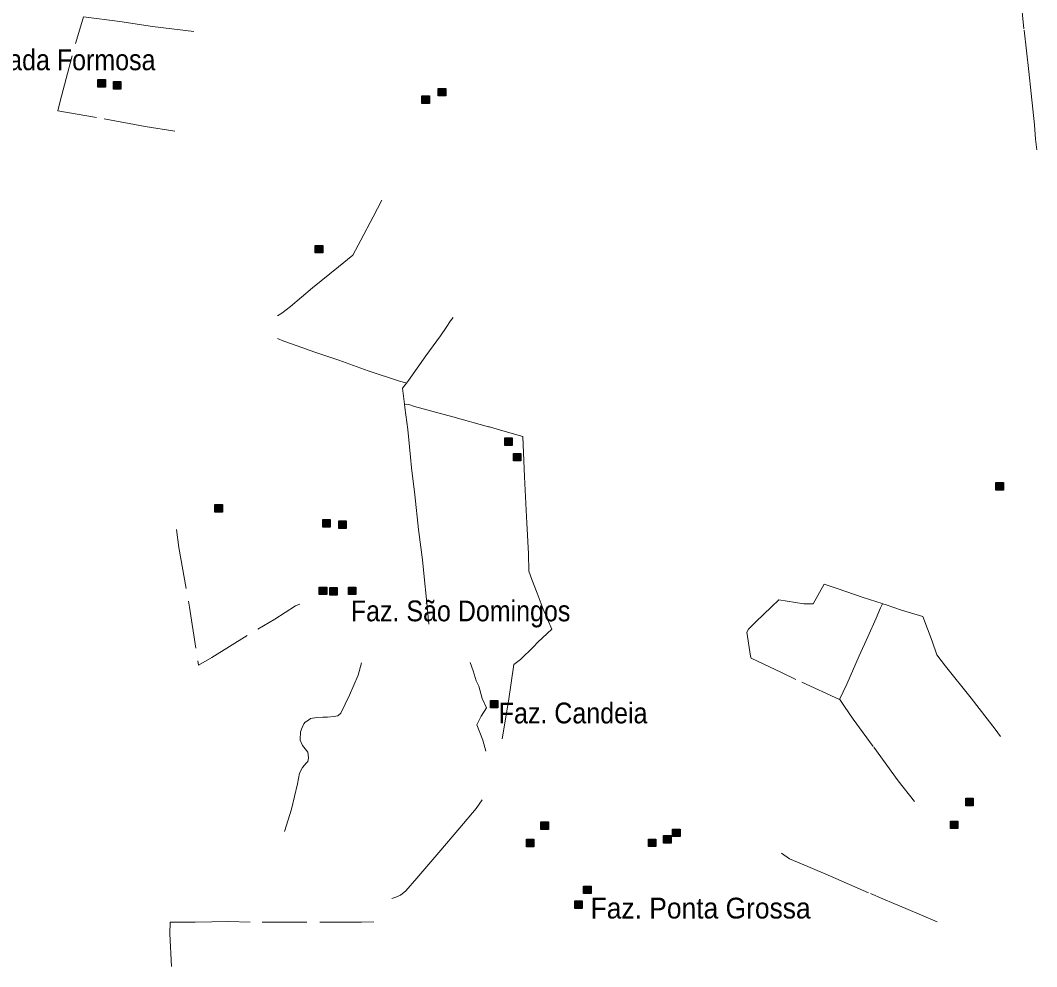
# Model space of a CAD drawing. Extents: x 393.5 to 446.9, y 8064.8 to 8120.4.
# Drawn here: x 430.01 to 437.84, y 8091.38 to 8098.67 of the extents above; entities that cross this region are included whole.
import ezdxf

# ---------------------------------------------------------------- set-up
doc = ezdxf.new("R2010")
doc.units = 0
doc.header["$LTSCALE"] = 0.064
doc.linetypes.add('DOT_DASHED', pattern=[7.7, 5, -1.2, 0.3, -1.2])
doc.layers.add('2', color=7, linetype='Continuous', lineweight=25)
doc.layers.add('22', color=7, linetype='DOT_DASHED', lineweight=13)
doc.layers.add('61', color=7, linetype='Continuous')

msp = doc.modelspace()

# ---------------------------------------------------------------- hatches: boundary and pattern name
at = {"layer": '2'}
for points in [[(430.6056, 8098.2137), (430.6636, 8098.2137), (430.6636, 8098.1557), (430.6056, 8098.1557)], [(430.7246, 8098.1996), (430.7826, 8098.1996), (430.7826, 8098.1416), (430.7246, 8098.1416)], [(433.2268, 8098.1458), (433.2848, 8098.1458), (433.2848, 8098.0878), (433.2268, 8098.0878)], [(433.1008, 8098.0892), (433.1588, 8098.0892), (433.1588, 8098.0312), (433.1008, 8098.0312)], [(432.2789, 8096.9379), (432.3369, 8096.9379), (432.3369, 8096.8799), (432.2789, 8096.8799)], [(433.7385, 8095.456), (433.7965, 8095.456), (433.7965, 8095.398), (433.7385, 8095.398)], [(433.8056, 8095.3362), (433.8636, 8095.3362), (433.8636, 8095.2782), (433.8056, 8095.2782)], [(437.522, 8095.111), (437.58, 8095.111), (437.58, 8095.053), (437.522, 8095.053)], [(431.5059, 8094.9421), (431.5639, 8094.9421), (431.5639, 8094.8841), (431.5059, 8094.8841)], [(432.3369, 8094.8273), (432.3949, 8094.8273), (432.3949, 8094.7693), (432.3369, 8094.7693)], [(432.4596, 8094.8166), (432.5176, 8094.8166), (432.5176, 8094.7586), (432.4596, 8094.7586)], [(432.3097, 8094.3073), (432.3677, 8094.3073), (432.3677, 8094.2493), (432.3097, 8094.2493)], [(432.3903, 8094.3038), (432.4483, 8094.3038), (432.4483, 8094.2458), (432.3903, 8094.2458)], [(432.5342, 8094.3072), (432.5922, 8094.3072), (432.5922, 8094.2492), (432.5342, 8094.2492)], [(433.6277, 8093.4344), (433.6857, 8093.4344), (433.6857, 8093.3764), (433.6277, 8093.3764)], [(437.2896, 8092.6815), (437.3476, 8092.6815), (437.3476, 8092.6235), (437.2896, 8092.6235)], [(434.0173, 8092.4991), (434.0753, 8092.4991), (434.0753, 8092.4411), (434.0173, 8092.4411)], [(437.1717, 8092.5062), (437.2297, 8092.5062), (437.2297, 8092.4482), (437.1717, 8092.4482)], [(435.0308, 8092.4444), (435.0888, 8092.4444), (435.0888, 8092.3864), (435.0308, 8092.3864)], [(433.9051, 8092.3654), (433.9631, 8092.3654), (433.9631, 8092.3074), (433.9051, 8092.3074)], [(434.8449, 8092.3677), (434.9029, 8092.3677), (434.9029, 8092.3097), (434.8449, 8092.3097)], [(434.9624, 8092.3941), (435.0204, 8092.3941), (435.0204, 8092.3361), (434.9624, 8092.3361)], [(434.3459, 8092.0051), (434.4039, 8092.0051), (434.4039, 8091.9471), (434.3459, 8091.9471)], [(434.2775, 8091.8914), (434.3355, 8091.8914), (434.3355, 8091.8334), (434.2775, 8091.8334)]]:
    msp.add_hatch(color=256, dxfattribs=at).paths.add_polyline_path(points)

# ---------------------------------------------------------------- linework, layer by layer
for points in [[(430.6056, 8098.2137), (430.6636, 8098.2137), (430.6636, 8098.1557), (430.6056, 8098.1557)], [(430.7246, 8098.1996), (430.7826, 8098.1996), (430.7826, 8098.1416), (430.7246, 8098.1416)], [(433.2268, 8098.1458), (433.2848, 8098.1458), (433.2848, 8098.0878), (433.2268, 8098.0878)], [(433.1008, 8098.0892), (433.1588, 8098.0892), (433.1588, 8098.0312), (433.1008, 8098.0312)], [(432.2789, 8096.9379), (432.3369, 8096.9379), (432.3369, 8096.8799), (432.2789, 8096.8799)], [(433.7385, 8095.456), (433.7965, 8095.456), (433.7965, 8095.398), (433.7385, 8095.398)], [(433.8056, 8095.3362), (433.8636, 8095.3362), (433.8636, 8095.2782), (433.8056, 8095.2782)], [(437.522, 8095.111), (437.58, 8095.111), (437.58, 8095.053), (437.522, 8095.053)], [(431.5059, 8094.9421), (431.5639, 8094.9421), (431.5639, 8094.8841), (431.5059, 8094.8841)], [(432.3369, 8094.8273), (432.3949, 8094.8273), (432.3949, 8094.7693), (432.3369, 8094.7693)], [(432.4596, 8094.8166), (432.5176, 8094.8166), (432.5176, 8094.7586), (432.4596, 8094.7586)], [(432.3097, 8094.3073), (432.3677, 8094.3073), (432.3677, 8094.2493), (432.3097, 8094.2493)], [(432.3903, 8094.3038), (432.4483, 8094.3038), (432.4483, 8094.2458), (432.3903, 8094.2458)], [(432.5342, 8094.3072), (432.5922, 8094.3072), (432.5922, 8094.2492), (432.5342, 8094.2492)], [(433.6277, 8093.4344), (433.6857, 8093.4344), (433.6857, 8093.3764), (433.6277, 8093.3764)], [(437.2896, 8092.6815), (437.3476, 8092.6815), (437.3476, 8092.6235), (437.2896, 8092.6235)], [(434.0173, 8092.4991), (434.0753, 8092.4991), (434.0753, 8092.4411), (434.0173, 8092.4411)], [(437.1717, 8092.5062), (437.2297, 8092.5062), (437.2297, 8092.4482), (437.1717, 8092.4482)], [(435.0308, 8092.4444), (435.0888, 8092.4444), (435.0888, 8092.3864), (435.0308, 8092.3864)], [(433.9051, 8092.3654), (433.9631, 8092.3654), (433.9631, 8092.3074), (433.9051, 8092.3074)], [(434.8449, 8092.3677), (434.9029, 8092.3677), (434.9029, 8092.3097), (434.8449, 8092.3097)], [(434.9624, 8092.3941), (435.0204, 8092.3941), (435.0204, 8092.3361), (434.9624, 8092.3361)], [(434.3459, 8092.0051), (434.4039, 8092.0051), (434.4039, 8091.9471), (434.3459, 8091.9471)], [(434.2775, 8091.8914), (434.3355, 8091.8914), (434.3355, 8091.8334), (434.2775, 8091.8334)]]:
    msp.add_lwpolyline(points, close=True, dxfattribs=at)
at = {"layer": '22'}
msp.add_line((431.9876, 8096.2199), (432.0361, 8096.1996), dxfattribs=at)
for points in [[(437.8357, 8097.6737), (437.8271, 8097.7543), (437.8185, 8097.8659), (437.7928, 8098.1062), (437.7741, 8098.2758), (437.738, 8098.6054), (437.6917, 8099.0375), (437.6488, 8099.4375), (437.6299, 8099.6201), (437.599, 8099.9016), (437.5689, 8100.1728), (437.5526, 8100.3514), (437.5277, 8100.6107), (437.4993, 8100.8236), (437.4873, 8100.9781), (437.459, 8101.2372), (437.4289, 8101.4999), (437.4194, 8101.608), (437.4194, 8101.6269), (437.4242, 8101.6408)], [(430.3236, 8098.0875), (430.4495, 8098.5517), (430.4937, 8098.6982), (430.7729, 8098.661), (431.0265, 8098.6238), (431.4407, 8098.5726)], [(431.1987, 8097.817), (430.9683, 8097.8542), (430.5937, 8097.9216), (430.2959, 8097.9727), (430.3075, 8098.0169), (430.3236, 8098.0875)], [(432.0883, 8096.4673), (432.2584, 8096.6114), (432.4585, 8096.7727), (432.5693, 8096.8631), (432.6296, 8096.9771), (432.7243, 8097.1577), (432.7921, 8097.2868)], [(431.9893, 8096.3964), (432.0216, 8096.4157), (432.0883, 8096.4673)], [(432.9811, 8095.8779), (432.9983, 8095.8966), (433.1319, 8096.0864), (433.2444, 8096.2426), (433.2882, 8096.3067), (433.321, 8096.3566), (433.3414, 8096.3816)], [(432.0361, 8096.1996), (432.1408, 8096.1652), (432.2752, 8096.1168), (432.4613, 8096.0528), (432.6856, 8095.9732), (432.9279, 8095.892), (432.9779, 8095.8788), (432.9811, 8095.8779)], [(432.9667, 8095.7159), (432.9514, 8095.8389), (432.9811, 8095.8779)], [(433.6131, 8095.5411), (433.3391, 8095.6178), (433.0444, 8095.6977), (433.0006, 8095.7133), (432.971, 8095.7156), (432.9667, 8095.7159)], [(433.0134, 8095.3062), (432.9922, 8095.5213), (432.9693, 8095.6897), (432.9667, 8095.7159)], [(433.9052, 8094.8482), (433.8909, 8095.1548), (433.8781, 8095.4654), (433.7969, 8095.4904), (433.6796, 8095.5232), (433.6202, 8095.5404), (433.6131, 8095.5411)], [(433.1537, 8094.0207), (433.1358, 8094.2103), (433.1186, 8094.3853), (433.1061, 8094.518), (433.0756, 8094.7492), (433.0467, 8095.0178), (433.0209, 8095.2255), (433.0134, 8095.3062)], [(433.7178, 8093.1388), (433.7677, 8093.4301), (433.8098, 8093.7112), (433.8598, 8093.7487), (433.9599, 8093.8471), (433.9942, 8093.883), (434.1016, 8093.9836), (434.0344, 8094.1366), (433.9891, 8094.26), (433.9476, 8094.3646), (433.9242, 8094.4287), (433.9227, 8094.5639), (433.9078, 8094.8028), (433.9052, 8094.8482)], [(431.2102, 8094.7493), (431.2296, 8094.6116), (431.3096, 8094.1533), (431.3788, 8093.706), (431.4825, 8093.7642), (431.8356, 8093.9842), (431.9676, 8094.0605), (432.1277, 8094.1624), (432.1605, 8094.1751)], [(436.3179, 8093.4414), (435.9816, 8093.5968), (435.871, 8093.649), (435.6374, 8093.7596), (435.632, 8093.7749), (435.6028, 8093.9592), (435.6167, 8093.9837), (435.675, 8094.0421), (435.7918, 8094.1526), (435.8494, 8094.2079), (436.0415, 8094.1787), (436.1137, 8094.1772), (436.1998, 8094.3292), (436.2996, 8094.2969), (436.5002, 8094.2278), (436.6465, 8094.1799), (436.6501, 8094.1787)], [(436.3179, 8093.4414), (436.3741, 8093.5605), (436.4694, 8093.777), (436.5347, 8093.9244), (436.5992, 8094.0687), (436.633, 8094.147), (436.6493, 8094.1771), (436.6498, 8094.1781), (436.6501, 8094.1787)], [(437.5564, 8093.1557), (437.5155, 8093.2136), (437.3301, 8093.4513), (437.1345, 8093.6977), (437.0672, 8093.7865), (437.0309, 8093.8898), (436.9581, 8094.0805), (436.7937, 8094.1296), (436.6769, 8094.1696), (436.6501, 8094.1787)], [(432.1645, 8093.1727), (432.1655, 8093.1923), (432.1792, 8093.2266), (432.1906, 8093.254), (432.2021, 8093.2677), (432.2272, 8093.2838), (432.2433, 8093.2953), (432.2914, 8093.3022), (432.3372, 8093.3069), (432.3739, 8093.3069), (432.4221, 8093.3116), (432.4518, 8093.3162), (432.4773, 8093.3355), (432.5422, 8093.4761), (432.6089, 8093.6292), (432.6342, 8093.7246)], [(433.4724, 8093.7253), (433.4942, 8093.6613), (433.5193, 8093.5848), (433.538, 8093.5442), (433.5646, 8093.4489), (433.5974, 8093.3786), (433.5575, 8093.3146), (433.5247, 8093.2475), (433.5693, 8093.1279), (433.5927, 8093.0451)], [(436.8946, 8092.6562), (436.7697, 8092.8155), (436.5771, 8093.0795), (436.423, 8093.2905), (436.3555, 8093.3865), (436.3192, 8093.4408), (436.3179, 8093.4414)], [(432.0413, 8092.4257), (432.0974, 8092.5969), (432.1431, 8092.7934), (432.159, 8092.8735), (432.1796, 8092.9169), (432.1956, 8092.9352), (432.2071, 8092.9489), (432.2208, 8092.9649), (432.2254, 8092.9763), (432.2277, 8092.99), (432.2254, 8093.0175), (432.2216, 8093.0355), (432.1801, 8093.0877), (432.1639, 8093.1291), (432.1639, 8093.1508), (432.1645, 8093.1727)], [(432.8692, 8091.9103), (432.9004, 8091.9202), (432.9352, 8091.935), (432.978, 8091.9688), (433.0625, 8092.0661), (433.232, 8092.2635), (433.3936, 8092.4543), (433.5186, 8092.6013), (433.5656, 8092.6698)], [(435.869, 8092.2589), (435.9322, 8092.2148), (436.0722, 8092.1558), (436.2467, 8092.081), (436.555, 8091.9471), (436.6519, 8091.9064)], [(436.6519, 8091.9064), (436.7356, 8091.8723), (436.8269, 8091.8329), (437.0683, 8091.7306)], [(432.7303, 8091.7311), (432.6342, 8091.7276), (432.1895, 8091.7276), (431.779, 8091.7276), (431.61, 8091.7315), (431.3535, 8091.7267), (431.1623, 8091.7286), (431.1603, 8091.6369), (431.1723, 8091.3849)]]:
    msp.add_lwpolyline(points, dxfattribs=at)

# ---------------------------------------------------------------- texts
at = {"layer": '61'}
for s, width, p in [('Faz. Pancada Formosa', 0.9, (429.0471, 8098.2862)), ('Faz. São Domingos', 0.9, (432.553, 8094.0437)), ('Faz. Candeia', 0.9, (433.6926, 8093.2577)), ('Faz. Ponta Grossa', 0.95, (434.4001, 8091.7556))]:
    msp.add_text(s, height=0.16, dxfattribs=dict(at, width=width)).set_placement(p)

doc.saveas('drawing.dxf')
